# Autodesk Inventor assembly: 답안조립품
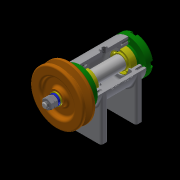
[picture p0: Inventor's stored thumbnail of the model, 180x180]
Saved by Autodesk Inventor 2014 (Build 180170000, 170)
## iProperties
Created: 2020-07
Part Number: 답안조립품
Document SubType Name: Assembly
Designer: kh
Author: kh
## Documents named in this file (14)
- C:\Users\kh\Desktop\700706V1020\답안조립품.iam
- C:\Users\kh\Desktop\700706V1020\본체.ipt
- C:\Users\kh\Desktop\700706V1020\베어링 6002.ipt
- C:\Users\kh\Desktop\700706V1020\뒤커버.ipt
- C:\Users\kh\Desktop\700706V1020\앞커버.ipt
- C:\Users\kh\Desktop\700706V1020\축.ipt
- C:\Users\kh\Desktop\700706V1020\오일 실 15 25 7.ipt
- C:\Users\kh\Desktop\700706V1020\키 3x3x12.ipt
- C:\Users\kh\Desktop\700706V1020\V벨트풀리.ipt
- C:\Users\kh\Desktop\700706V1020\와셔 8x17.ipt
- C:\Users\kh\Desktop\700706V1020\스프링와셔 8.ipt
- C:\Users\kh\Desktop\700706V1020\너트 M8.ipt
- C:\Users\kh\Desktop\700706V1020\와셔 6x11.5.ipt
- C:\Users\kh\Desktop\700706V1020\볼트 M6x8.ipt
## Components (1 placed, 1 different names)
1. V벨트풀리:1 — Mate:17, Mate:18, Mate:20, Mate:25
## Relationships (4: Mate 4)
- Mate:17: V벨트풀리:1
- Mate:18: V벨트풀리:1
- Mate:20: V벨트풀리:1
- Mate:25: V벨트풀리:1
